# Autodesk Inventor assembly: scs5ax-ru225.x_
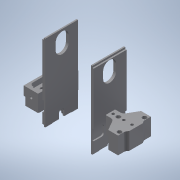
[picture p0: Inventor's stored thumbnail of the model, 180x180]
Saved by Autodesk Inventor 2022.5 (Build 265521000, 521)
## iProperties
Part Number: scs5ax-ru225.x_
Material: 一般
Document SubType Name: Assembly
Designer: ImaoCorp
Sending System: SOLIDWORKS 2017-2017317
MC: AMD64
MC_MODEL: Intel64 Family 6 Model 60 Stepping 3, GenuineIntel
OS: Windows_NT
FRU: Parasolid Version 29.0, build 201,  4-17-2017
FORMAT: text
GUISE: transmit
KEY: scs5ax-ru225
FILE: scs5ax-ru225.x_t
DATE: Wed Sep 18 16:18:32 2019
Author: ImaoCorp
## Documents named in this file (5)
- X:\14_SW2022-Inv2022\00_全2023-1023新製品(TCC)まで\s\scs5ax-ru225\SCS5AX-RU225.iam
- X:\14_SW2022-Inv2022\00_全2023-1023新製品(TCC)まで\s\scs5ax-ru225\scs5ax-ru225_01.ipt
- X:\14_SW2022-Inv2022\00_全2023-1023新製品(TCC)まで\s\scs5ax-ru225\scs5ax-ru225_02.ipt
- X:\14_SW2022-Inv2022\00_全2023-1023新製品(TCC)まで\s\scs5ax-ru225\scs5ax-ru225_03.ipt
- X:\14_SW2022-Inv2022\00_全2023-1023新製品(TCC)まで\s\scs5ax-ru225\scs5ax-ru225_04.ipt
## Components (4 placed, 4 different names)
1. scs5ax-ru225_01
2. scs5ax-ru225_02
3. scs5ax-ru225_03
4. scs5ax-ru225_04
